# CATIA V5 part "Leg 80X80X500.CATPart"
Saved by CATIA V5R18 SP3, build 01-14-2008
Part number: Leg(80X80X500)
Bounding box of the stored display mesh (mm): x -40 to 40, y -40 to 40, z 0 to 500
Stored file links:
  E:\#00 CATIA V5 Movie\#03 CATIA V5 Data\#07 KIN\Balance Unit (1)\Leg 80X80X500.CATPart
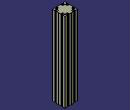
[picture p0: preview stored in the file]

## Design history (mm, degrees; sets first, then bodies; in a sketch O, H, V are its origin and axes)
Body1 "PartBody" (main body)
  Solid1: solid without history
